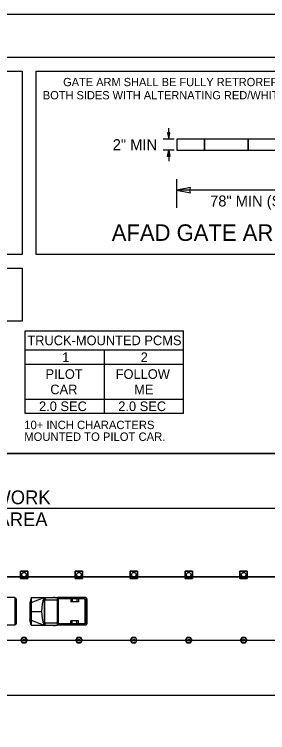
# Model space of a CAD drawing. Extents: x 99999.1 to 100095.7, y 99995 to 100010.7.
# Drawn here: x 100047.48 to 100049.33, y 100005.46 to 100010.69 of the extents above; entities that cross this region are included whole.
import ezdxf

# ---------------------------------------------------------------- set-up
doc = ezdxf.new("R2010")
doc.units = 0
for name, color, linetype in [('RD_ED_ShoulderPavedEdge', 7, 'Continuous'), ('RD_MK_LineEdgeWhite', 7, 'Continuous'), ('RD_MK_LineSkipCenter', 7, 'Continuous'), ('SH_GI_PlotLimits', 7, 'Continuous'), ('SH_GI_SheetBorder', 7, 'Continuous'), ('SH_TI_Tables', 7, 'Continuous'), ('TR_WZ_MotoristVehicle', 7, 'Continuous'), ('TR_WZ_PortableChangeMessageSign', 7, 'Continuous'), ('TR_WZ_TrafficCone', 7, 'Continuous'), ('TR_WZ_TubularMarker', 7, 'Continuous'), ('TR_WZ_WorkAreaLabel', 7, 'Continuous'), ('TR_WZ_WorkZoneDetails', 7, 'Continuous')]:
    doc.layers.add(name, color=color, linetype=linetype)

msp = doc.modelspace()

# ---------------------------------------------------------------- linework, layer by layer
at = {"layer": 'RD_ED_ShoulderPavedEdge'}
for p, q in [((100040.1076, 100007.4923), (100055.6424, 100007.4923)), ((100040.1076, 100005.7323), (100055.6424, 100005.7323))]:
    msp.add_line(p, q, dxfattribs=at)
at = {"layer": 'RD_MK_LineEdgeWhite'}
for p, q in [((100040.1076, 100007.0923), (100055.6424, 100007.0923)), ((100040.1076, 100006.1323), (100055.6424, 100006.1323))]:
    msp.add_line(p, q, dxfattribs=at)
at = {"layer": 'RD_MK_LineSkipCenter'}
msp.add_lwpolyline([(100051.15, 100006.5923), (100043.4767, 100006.5923)], dxfattribs=at)
at = {"layer": 'SH_GI_PlotLimits'}
msp.add_lwpolyline([(100039.0625, 99999.6875), (100056.0625, 99999.6875), (100056.0625, 100010.6875), (100039.0625, 100010.6875)], close=True, dxfattribs=at)
at = {"layer": 'SH_GI_SheetBorder'}
msp.add_line((100040, 100010.375), (100055.75, 100010.375), dxfattribs=at)
at = {"layer": 'SH_TI_Tables'}
msp.add_lwpolyline([(100045.0739, 100008.839), (100047.5374, 100008.839), (100047.5374, 100008.455), (100045.0739, 100008.455)], close=True, dxfattribs=at)
at = {"layer": 'TR_WZ_MotoristVehicle'}
for p, q in [((100047.4829, 100006.4423), (100047.2772, 100006.4423)), ((100047.4829, 100006.4423), (100047.4829, 100006.2423)), ((100047.4881, 100006.439), (100047.4836, 100006.439)), ((100047.4836, 100006.439), (100047.4836, 100006.2456)), ((100047.4926, 100006.4329), (100047.4926, 100006.2517)), ((100047.6018, 100006.4423), (100047.5926, 100006.402)), ((100047.5926, 100006.402), (100047.5926, 100006.2827)), ((100047.6018, 100006.4423), (100047.6018, 100006.2423)), ((100047.6018, 100006.4423), (100047.7907, 100006.4423)), ((100047.6018, 100006.4057), (100047.6963, 100006.4423)), ((100047.6963, 100006.4423), (100047.6963, 100006.2423)), ((100047.698, 100006.4423), (100047.698, 100006.2423)), ((100047.698, 100006.4423), (100047.71, 100006.4268)), ((100047.698, 100006.4268), (100047.7907, 100006.4268)), ((100047.765, 100006.4451), (100047.7763, 100006.4451)), ((100047.7907, 100006.4423), (100047.7907, 100006.2423)), ((100047.9992, 100006.4423), (100047.7935, 100006.4423)), ((100047.7935, 100006.4423), (100047.7935, 100006.2423)), ((100047.9934, 100006.4344), (100047.7993, 100006.4344)), ((100047.7993, 100006.4344), (100047.7993, 100006.2503)), ((100047.892, 100006.4344), (100047.892, 100006.4113)), ((100047.947, 100006.4113), (100047.892, 100006.4113)), ((100047.902, 100006.4344), (100047.902, 100006.4113)), ((100047.936, 100006.4344), (100047.936, 100006.4113)), ((100047.947, 100006.4344), (100047.947, 100006.4113)), ((100047.9934, 100006.4344), (100047.9934, 100006.2503)), ((100047.9992, 100006.4423), (100047.9992, 100006.2423)), ((100048.0044, 100006.439), (100047.9999, 100006.439)), ((100047.9999, 100006.439), (100047.9999, 100006.2456)), ((100048.0088, 100006.4329), (100048.0088, 100006.2517)), ((100047.4926, 100006.3564), (100047.4836, 100006.3527)), ((100048.0088, 100006.3564), (100047.9999, 100006.3527)), ((100047.4926, 100006.3282), (100047.4836, 100006.332)), ((100047.4902, 100006.3423), (100047.486, 100006.3423)), ((100047.4881, 100006.3451), (100047.4881, 100006.3395)), ((100047.6018, 100006.3423), (100047.6777, 100006.3423)), ((100048.0088, 100006.3282), (100047.9999, 100006.332)), ((100048.0064, 100006.3423), (100048.0023, 100006.3423)), ((100048.0044, 100006.3451), (100048.0044, 100006.3395)), ((100047.4829, 100006.2423), (100047.2772, 100006.2423)), ((100047.4881, 100006.2456), (100047.4836, 100006.2456)), ((100047.6018, 100006.2423), (100047.5926, 100006.2827)), ((100047.6018, 100006.279), (100047.6963, 100006.2423)), ((100047.6018, 100006.2423), (100047.7907, 100006.2423)), ((100047.698, 100006.2578), (100047.7907, 100006.2578)), ((100047.708, 100006.2578), (100047.698, 100006.2423)), ((100047.9992, 100006.2423), (100047.7935, 100006.2423)), ((100047.9934, 100006.2503), (100047.7993, 100006.2503)), ((100047.892, 100006.2503), (100047.892, 100006.2733)), ((100047.947, 100006.2733), (100047.892, 100006.2733)), ((100047.902, 100006.2503), (100047.902, 100006.2733)), ((100047.936, 100006.2503), (100047.936, 100006.2733)), ((100047.947, 100006.2503), (100047.947, 100006.2733)), ((100048.0044, 100006.2456), (100047.9999, 100006.2456)), ((100047.765, 100006.2395), (100047.7763, 100006.2395))]:
    msp.add_line(p, q, dxfattribs=at)
for centre, major_axis, start_param, end_param in [((100047.4881, 100006.4329), (0, 0.0061), 4.712389, 6.283185), ((100047.8313, 100006.3423), (0, -0.2099), 4.215667, 5.208926), ((100048.0044, 100006.4329), (0, 0.0061), 4.712389, 6.283185), ((100047.4881, 100006.2517), (0, -0.0061), 0, 1.570796), ((100048.0044, 100006.2517), (0, -0.0061), 0, 1.570796)]:
    msp.add_ellipse(centre, major_axis=major_axis, ratio=0.73155, start_param=start_param, end_param=end_param, dxfattribs=at)
for centre in [(100047.4881, 100006.3423), (100048.0044, 100006.3423)]:
    msp.add_ellipse(centre, major_axis=(0, 0.00282), ratio=0.73155, dxfattribs=at)
at = {"layer": 'TR_WZ_PortableChangeMessageSign'}
for p, q in [((100047.5582, 100008.3845), (100048.7132, 100008.3845)), ((100047.5582, 100007.7825), (100047.5582, 100008.3845)), ((100048.7132, 100007.7825), (100048.7132, 100008.3845)), ((100048.7132, 100008.2445), (100047.5582, 100008.2445)), ((100048.1357, 100007.7825), (100048.1357, 100008.2445)), ((100048.1357, 100008.1395), (100047.5582, 100008.1395)), ((100048.7132, 100008.1395), (100048.1357, 100008.1395)), ((100047.5582, 100007.8875), (100048.1357, 100007.8875)), ((100048.1357, 100007.8875), (100048.7132, 100007.8875)), ((100048.7132, 100007.7825), (100047.5582, 100007.7825))]:
    msp.add_line(p, q, dxfattribs=at)
at = {"layer": 'TR_WZ_TrafficCone'}
for points in [[(100047.5234, 100006.6357), (100047.5767, 100006.6357), (100047.5767, 100006.5823), (100047.5234, 100006.5823), (100047.5234, 100006.6357)], [(100047.5234, 100006.5823), (100047.5767, 100006.5823), (100047.5767, 100006.6357), (100047.5234, 100006.6357), (100047.5234, 100006.5823)], [(100047.9234, 100006.6357), (100047.9767, 100006.6357), (100047.9767, 100006.5823), (100047.9234, 100006.5823), (100047.9234, 100006.6357)], [(100047.9234, 100006.5823), (100047.9767, 100006.5823), (100047.9767, 100006.6357), (100047.9234, 100006.6357), (100047.9234, 100006.5823)], [(100048.3234, 100006.6357), (100048.3767, 100006.6357), (100048.3767, 100006.5823), (100048.3234, 100006.5823), (100048.3234, 100006.6357)], [(100048.3234, 100006.5823), (100048.3767, 100006.5823), (100048.3767, 100006.6357), (100048.3234, 100006.6357), (100048.3234, 100006.5823)], [(100048.7234, 100006.6357), (100048.7767, 100006.6357), (100048.7767, 100006.5823), (100048.7234, 100006.5823), (100048.7234, 100006.6357)], [(100048.7234, 100006.5823), (100048.7767, 100006.5823), (100048.7767, 100006.6357), (100048.7234, 100006.6357), (100048.7234, 100006.5823)], [(100049.1234, 100006.6357), (100049.1767, 100006.6357), (100049.1767, 100006.5823), (100049.1234, 100006.5823), (100049.1234, 100006.6357)], [(100049.1234, 100006.5823), (100049.1767, 100006.5823), (100049.1767, 100006.6357), (100049.1234, 100006.6357), (100049.1234, 100006.5823)]]:
    msp.add_lwpolyline(points, dxfattribs=at)
for centre in [(100047.55, 100006.609), (100047.95, 100006.609), (100048.35, 100006.609), (100048.75, 100006.609), (100049.15, 100006.609)]:
    msp.add_circle(centre, 0.0167, dxfattribs=at)
at = {"layer": 'TR_WZ_TubularMarker'}
for points in [[(100047.5269, 100006.1323), (100047.5385, 100006.1523), (100047.5616, 100006.1523), (100047.5731, 100006.1323), (100047.5616, 100006.1123), (100047.5385, 100006.1123)], [(100047.9269, 100006.1323), (100047.9385, 100006.1523), (100047.9616, 100006.1523), (100047.9731, 100006.1323), (100047.9616, 100006.1123), (100047.9385, 100006.1123)], [(100048.3269, 100006.1323), (100048.3385, 100006.1523), (100048.3616, 100006.1523), (100048.3731, 100006.1323), (100048.3616, 100006.1123), (100048.3385, 100006.1123)], [(100048.7269, 100006.1323), (100048.7385, 100006.1523), (100048.7616, 100006.1523), (100048.7731, 100006.1323), (100048.7616, 100006.1123), (100048.7385, 100006.1123)], [(100049.1269, 100006.1323), (100049.1385, 100006.1523), (100049.1616, 100006.1523), (100049.1731, 100006.1323), (100049.1616, 100006.1123), (100049.1385, 100006.1123)]]:
    msp.add_lwpolyline(points, close=True, dxfattribs=at)
for points in [[(100047.5385, 100006.1123), (100047.5616, 100006.1123), (100047.5731, 100006.1323), (100047.5616, 100006.1523), (100047.5385, 100006.1523), (100047.5269, 100006.1323), (100047.5385, 100006.1123)], [(100047.9385, 100006.1123), (100047.9616, 100006.1123), (100047.9731, 100006.1323), (100047.9616, 100006.1523), (100047.9385, 100006.1523), (100047.9269, 100006.1323), (100047.9385, 100006.1123)], [(100048.3385, 100006.1123), (100048.3616, 100006.1123), (100048.3731, 100006.1323), (100048.3616, 100006.1523), (100048.3385, 100006.1523), (100048.3269, 100006.1323), (100048.3385, 100006.1123)], [(100048.7385, 100006.1123), (100048.7616, 100006.1123), (100048.7731, 100006.1323), (100048.7616, 100006.1523), (100048.7385, 100006.1523), (100048.7269, 100006.1323), (100048.7385, 100006.1123)], [(100049.1385, 100006.1123), (100049.1616, 100006.1123), (100049.1731, 100006.1323), (100049.1616, 100006.1523), (100049.1385, 100006.1523), (100049.1269, 100006.1323), (100049.1385, 100006.1123)]]:
    msp.add_lwpolyline(points, dxfattribs=at)
for centre in [(100047.55, 100006.1323), (100047.95, 100006.1323), (100048.35, 100006.1323), (100048.75, 100006.1323), (100049.15, 100006.1323)]:
    msp.add_circle(centre, 0.00667, dxfattribs=at)
at = {"layer": 'TR_WZ_WorkZoneDetails'}
for p, q in [((100048.6043, 100009.779), (100048.6043, 100009.859)), ((100048.6443, 100009.779), (100048.5643, 100009.779)), ((100048.6443, 100009.699), (100048.5643, 100009.699)), ((100048.6043, 100009.699), (100048.6043, 100009.619)), ((100048.6643, 100009.279), (100048.6643, 100009.489)), ((100050.4643, 100009.409), (100048.6643, 100009.409))]:
    msp.add_line(p, q, dxfattribs=at)
for points in [[(100043.7984, 100010.275), (100047.5374, 100010.275), (100047.5374, 100008.939), (100043.7984, 100008.939)], [(100047.6374, 100010.275), (100050.9639, 100010.275), (100050.9639, 100008.939), (100047.6374, 100008.939)], [(100048.6043, 100009.779), (100048.6136, 100009.8262), (100048.6043, 100009.824), (100048.5951, 100009.8262)], [(100048.6043, 100009.699), (100048.6136, 100009.6518), (100048.6043, 100009.654), (100048.5951, 100009.6518)], [(100048.6643, 100009.409), (100048.7626, 100009.3897), (100048.7581, 100009.409), (100048.7626, 100009.4283)], [(100045.15, 100007.4923), (100045.15, 100006.5923), (100049.9338, 100006.5923), (100049.9338, 100007.4923)]]:
    msp.add_lwpolyline(points, close=True, dxfattribs=at)
for points in [[(100048.6643, 100009.699), (100048.8643, 100009.699), (100048.8643, 100009.779), (100048.6643, 100009.779), (100048.6643, 100009.699)], [(100050.4643, 100009.779), (100048.6643, 100009.779), (100048.6643, 100009.699), (100050.4643, 100009.699), (100050.4643, 100009.779)], [(100048.8643, 100009.699), (100049.1843, 100009.699), (100049.1843, 100009.779), (100048.8643, 100009.779), (100048.8643, 100009.699)], [(100049.1843, 100009.699), (100049.5043, 100009.699), (100049.5043, 100009.779), (100049.1843, 100009.779), (100049.1843, 100009.699)]]:
    msp.add_lwpolyline(points, dxfattribs=at)

# ---------------------------------------------------------------- texts
at = {"layer": 'TR_WZ_PortableChangeMessageSign'}
for s, height, p in [('TRUCK-MOUNTED PCMS', 0.07, (100047.5742, 100008.2795)), ('2', 0.07, (100048.4, 100008.157)), ('1', 0.07, (100047.8285, 100008.157)), ('PILOT', 0.07, (100047.707, 100008.0345)), ('FOLLOW', 0.07, (100048.2178, 100008.0345)), ('CAR', 0.07, (100047.7414, 100007.9225)), ('ME', 0.07, (100048.3525, 100007.9225)), ('2.0 SEC', 0.07, (100047.6593, 100007.8)), ('2.0 SEC', 0.07, (100048.2368, 100007.8)), ('10+ INCH CHARACTERS', 0.06125, (100047.5517, 100007.6687)), ('MOUNTED TO PILOT CAR.', 0.06125, (100047.5517, 100007.583))]:
    msp.add_text(s, height=height, rotation=360, dxfattribs=at).set_placement(p)
at = {"layer": 'TR_WZ_WorkAreaLabel'}
for s, p in [('WORK', (100047.3273, 100007.1223)), ('AREA', (100047.357, 100006.9623))]:
    msp.add_text(s, height=0.1, dxfattribs=at).set_placement(p)
at = {"layer": 'TR_WZ_WorkZoneDetails'}
for s, height, p in [('GATE ARM SHALL BE FULLY RETROREFLECTIVE ON', 0.06, (100047.8352, 100010.165)), ('BOTH SIDES WITH ALTERNATING RED/WHITE SHEETING', 0.06, (100047.6874, 100010.069)), ('78" MIN (SEE NOTE 13)', 0.08, (100048.9061, 100009.289))]:
    msp.add_text(s, height=height, dxfattribs=at).set_placement(p)
for s, height, p in [('2" MIN', 0.08, (100048.1966, 100009.699)), ('AFAD GATE ARM DETAIL', 0.12, (100048.1893, 100009.039))]:
    msp.add_text(s, height=height, rotation=360, dxfattribs=at).set_placement(p)

doc.saveas('drawing.dxf')
